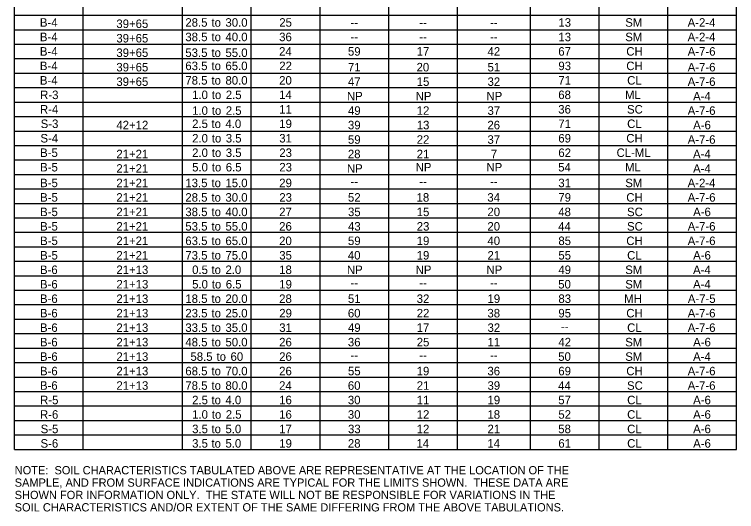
# Model space of a CAD drawing. Extents: x 977434 to 989596, y 1525697 to 1528336.
# Drawn here: x 977441 to 977967, y 1527523 to 1527885 of the extents above; entities that cross this region are included whole.
import ezdxf

# ---------------------------------------------------------------- set-up
doc = ezdxf.new("R2010")
doc.units = 0
doc.layers.add('Default', color=7, linetype='Continuous')

msp = doc.modelspace()

# ---------------------------------------------------------------- linework, layer by layer
at = {"layer": 'Default'}
for p, q in [((977441.26, 1527568.31), (977441.26, 1528234.33)), ((977441.26, 1527568.31), (977441.26, 1528234.33)), ((977966.88, 1527568.31), (977966.88, 1528234.33)), ((977966.88, 1527568.31), (977966.88, 1528234.33)), ((977491.28, 1527568.31), (977491.28, 1528221.17)), ((977563.67, 1527568.31), (977563.67, 1528221.17)), ((977613.69, 1527568.31), (977613.69, 1528221.17)), ((977663.71, 1527568.31), (977663.71, 1528221.17)), ((977816.83, 1527568.31), (977816.83, 1528221.17)), ((977866.85, 1527568.31), (977866.85, 1528221.17)), ((977916.87, 1527568.31), (977916.87, 1528221.17)), ((977713.72, 1527568.31), (977713.72, 1528210.64)), ((977763.74, 1527568.31), (977763.74, 1528210.64)), ((977441.26, 1527884.21), (977966.88, 1527884.21)), ((977441.26, 1527873.68), (977966.88, 1527873.68)), ((977441.26, 1527863.15), (977966.88, 1527863.15)), ((977441.26, 1527852.62), (977966.88, 1527852.62)), ((977441.26, 1527842.09), (977966.88, 1527842.09)), ((977441.26, 1527831.56), (977966.88, 1527831.56)), ((977441.26, 1527821.03), (977966.88, 1527821.03)), ((977441.26, 1527810.5), (977966.88, 1527810.5)), ((977441.26, 1527799.97), (977966.88, 1527799.97)), ((977441.26, 1527789.44), (977966.88, 1527789.44)), ((977441.26, 1527778.91), (977966.88, 1527778.91)), ((977441.26, 1527768.38), (977966.88, 1527768.38)), ((977441.26, 1527757.85), (977966.88, 1527757.85)), ((977441.26, 1527747.32), (977966.88, 1527747.32)), ((977441.26, 1527736.79), (977966.88, 1527736.79)), ((977441.26, 1527726.26), (977966.88, 1527726.26)), ((977441.26, 1527715.73), (977966.88, 1527715.73)), ((977441.26, 1527705.2), (977966.88, 1527705.2)), ((977441.26, 1527694.67), (977966.88, 1527694.67)), ((977441.26, 1527684.14), (977966.88, 1527684.14)), ((977441.26, 1527673.61), (977966.88, 1527673.61)), ((977441.26, 1527663.08), (977966.88, 1527663.08)), ((977441.26, 1527652.55), (977966.88, 1527652.55)), ((977441.26, 1527642.02), (977966.88, 1527642.02)), ((977441.26, 1527631.49), (977966.88, 1527631.49)), ((977441.26, 1527620.96), (977966.88, 1527620.96)), ((977441.26, 1527610.43), (977966.88, 1527610.43)), ((977441.26, 1527599.9), (977966.88, 1527599.9)), ((977441.26, 1527589.37), (977966.88, 1527589.37)), ((977441.26, 1527578.84), (977966.88, 1527578.84)), ((977441.26, 1527568.31), (977966.88, 1527568.31))]:
    msp.add_line(p, q, dxfattribs=at)

# ---------------------------------------------------------------- texts
for s, height, p in [('B-4', 6.188, (977459.79, 1527875.85)), ('39+65', 6.188, (977515.45, 1527874.92)), ('28.5', 6.188, (977565.66, 1527875.85)), (' to', 6.188, (977582.37, 1527875.85)), (' 30.0', 6.188, (977592.55, 1527875.85)), ('25', 6.188, (977634.04, 1527875.85)), ('13', 6.188, (977837.2, 1527875.85)), ('SM', 6.188, (977885.86, 1527875.85)), ('A-2-4', 6.188, (977931.27, 1527875.85)), ('--', 6.188, (977685.89, 1527875.85)), ('--', 6.188, (977735.91, 1527875.85)), ('--', 6.188, (977787.46, 1527875.85)), ('B-4', 6.188, (977459.79, 1527865.32)), ('39+65', 6.188, (977515.45, 1527864.39)), ('38.5', 6.188, (977565.66, 1527865.32)), (' to', 6.188, (977582.37, 1527865.32)), (' 40.0', 6.188, (977592.55, 1527865.32)), ('36', 6.188, (977633.95, 1527865.32)), ('13', 6.188, (977837.2, 1527865.32)), ('SM', 6.188, (977885.86, 1527865.32)), ('A-2-4', 6.188, (977931.27, 1527865.32)), ('--', 6.188, (977685.89, 1527865.32)), ('--', 6.188, (977735.91, 1527865.32)), ('--', 6.188, (977787.46, 1527865.32)), ('B-4', 6.188, (977459.79, 1527854.79)), ('39+65', 6.188, (977515.45, 1527853.86)), ('53.5', 6.188, (977565.66, 1527853.86)), (' to', 6.188, (977582.37, 1527853.86)), (' 55.0', 6.188, (977592.55, 1527853.86)), ('24', 6.188, (977633.9, 1527854.79)), ('59', 6.188, (977684.02, 1527854.79)), ('17', 6.188, (977734.02, 1527854.79)), ('42', 6.188, (977785.62, 1527854.79)), ('67', 6.188, (977837.12, 1527854.79)), ('CH', 6.188, (977886.63, 1527854.79)), ('A-7-6', 6.188, (977931.32, 1527854.79)), ('B-4', 6.188, (977459.79, 1527844.26)), ('39+65', 6.188, (977515.45, 1527843.33)), ('63.5', 6.188, (977565.66, 1527844.26)), (' to', 6.188, (977582.37, 1527844.26)), (' 65.0', 6.188, (977592.55, 1527844.26)), ('22', 6.188, (977634.03, 1527844.26)), ('71', 6.188, (977684.04, 1527843.33)), ('20', 6.188, (977733.96, 1527843.33)), ('51', 6.188, (977785.61, 1527843.33)), ('93', 6.188, (977837.2, 1527844.26)), ('CH', 6.188, (977886.63, 1527844.26)), ('A-7-6', 6.188, (977931.32, 1527843.33)), ('B-4', 6.188, (977459.79, 1527833.73)), ('39+65', 6.188, (977515.45, 1527832.8)), ('78.5', 6.188, (977565.66, 1527833.73)), (' to', 6.188, (977582.37, 1527833.73)), (' 80.0', 6.188, (977592.55, 1527833.73)), ('20', 6.188, (977633.93, 1527833.73)), ('47', 6.188, (977684, 1527832.8)), ('15', 6.188, (977734.08, 1527832.8)), ('32', 6.188, (977785.62, 1527832.8)), ('71', 6.188, (977837.16, 1527833.73)), ('CL', 6.188, (977887.25, 1527833.73)), ('A-7-6', 6.188, (977931.32, 1527832.8)), ('R-3', 6.188, (977459.96, 1527823.2)), ('1.0', 6.188, (977570.6, 1527823.2)), (' to', 6.188, (977582.61, 1527823.2)), (' 2.5', 6.188, (977592.78, 1527823.2)), ('14', 6.188, (977633.9, 1527823.2)), ('NP', 6.188, (977683.27, 1527822.27)), ('NP', 6.188, (977733.29, 1527822.27)), ('NP', 6.188, (977784.84, 1527822.27)), ('68', 6.188, (977837.1, 1527823.2)), ('ML', 6.188, (977885.68, 1527823.2)), ('A-4', 6.188, (977935.23, 1527822.27)), ('R-4', 6.188, (977459.8, 1527812.67)), ('1.0', 6.188, (977570.6, 1527811.74)), (' to', 6.188, (977582.61, 1527811.74)), (' 2.5', 6.188, (977592.78, 1527811.74)), ('11', 6.188, (977634.02, 1527812.67)), ('49', 6.188, (977684.02, 1527811.74)), ('12', 6.188, (977734.06, 1527811.74)), ('37', 6.188, (977785.57, 1527811.74)), ('36', 6.188, (977837.09, 1527812.67)), ('SC', 6.188, (977887.15, 1527812.67)), ('A-7-6', 6.188, (977931.32, 1527811.74)), ('S-3', 6.188, (977460.36, 1527802.14)), ('42+12', 6.188, (977515.44, 1527801.21)), ('2.5', 6.188, (977570.6, 1527802.14)), (' to', 6.188, (977582.37, 1527802.14)), (' 4.0', 6.188, (977592.55, 1527802.14)), ('19', 6.188, (977634.01, 1527802.14)), ('39', 6.188, (977684.02, 1527801.21)), ('13', 6.188, (977734.09, 1527801.21)), ('26', 6.188, (977785.54, 1527801.21)), ('71', 6.188, (977837.16, 1527802.14)), ('CL', 6.188, (977887.25, 1527802.14)), ('A-6', 6.188, (977935.28, 1527801.21)), ('S-4', 6.188, (977460.21, 1527791.61)), ('2.0', 6.188, (977570.6, 1527791.61)), (' to', 6.188, (977582.61, 1527791.61)), (' 3.5', 6.188, (977592.78, 1527791.61)), ('31', 6.188, (977634.02, 1527791.61)), ('59', 6.188, (977684.02, 1527790.68)), ('22', 6.188, (977734.06, 1527790.68)), ('37', 6.188, (977785.57, 1527790.68)), ('69', 6.188, (977837.15, 1527791.61)), ('CH', 6.188, (977886.63, 1527791.61)), ('A-7-6', 6.188, (977931.32, 1527790.68)), ('B-5', 6.188, (977459.94, 1527781.08)), ('21+21', 6.188, (977515.43, 1527780.15)), ('2.0', 6.188, (977570.6, 1527781.08)), (' to', 6.188, (977582.61, 1527781.08)), (' 3.5', 6.188, (977592.78, 1527781.08)), ('23', 6.188, (977634.06, 1527781.08)), ('28', 6.188, (977683.98, 1527780.15)), ('21', 6.188, (977734.06, 1527780.15)), ('7', 6.19, (977788.04, 1527780.15)), ('62', 6.188, (977837.17, 1527781.08)), ('CL-ML', 6.188, (977879.54, 1527781.08)), ('A-4', 6.188, (977935.23, 1527780.15)), ('B-5', 6.188, (977459.94, 1527770.55)), ('21+21', 6.188, (977515.43, 1527769.62)), ('5.0', 6.188, (977570.6, 1527770.55)), (' to', 6.188, (977582.61, 1527770.55)), (' 6.5', 6.188, (977592.78, 1527770.55)), ('23', 6.188, (977634.06, 1527770.55)), ('NP', 6.188, (977683.27, 1527769.62)), ('NP', 6.188, (977733.29, 1527770.55)), ('NP', 6.188, (977784.84, 1527770.55)), ('54', 6.188, (977837.04, 1527770.55)), ('ML', 6.188, (977885.68, 1527770.55)), ('A-4', 6.188, (977935.23, 1527769.62)), ('B-5', 6.188, (977459.94, 1527759.09)), ('21+21', 6.188, (977515.43, 1527759.09)), ('13.5', 6.188, (977565.66, 1527759.09)), (' to', 6.188, (977582.37, 1527759.09)), (' 15.0', 6.188, (977592.55, 1527759.09)), ('29', 6.188, (977634.01, 1527759.09)), ('31', 6.188, (977837.16, 1527759.09)), ('SM', 6.188, (977885.86, 1527759.09)), ('A-2-4', 6.188, (977931.27, 1527759.09)), ('--', 6.188, (977685.89, 1527760.02)), ('--', 6.188, (977735.91, 1527760.02)), ('--', 6.188, (977787.46, 1527760.02)), ('B-5', 6.188, (977459.94, 1527748.56)), ('21+21', 6.188, (977515.43, 1527748.56)), ('28.5', 6.188, (977565.66, 1527748.56)), (' to', 6.188, (977582.37, 1527748.56)), (' 30.0', 6.188, (977592.55, 1527748.56)), ('23', 6.188, (977634.06, 1527748.56)), ('52', 6.188, (977684.05, 1527748.56)), ('18', 6.188, (977733.99, 1527748.56)), ('34', 6.188, (977785.49, 1527748.56)), ('79', 6.188, (977837.15, 1527748.56)), ('CH', 6.188, (977886.63, 1527748.56)), ('A-7-6', 6.188, (977931.32, 1527748.56)), ('B-5', 6.188, (977459.94, 1527738.03)), ('21+21', 6.188, (977515.43, 1527738.03)), ('38.5', 6.188, (977565.66, 1527738.03)), (' to', 6.188, (977582.37, 1527738.03)), (' 40.0', 6.188, (977592.55, 1527738.03)), ('27', 6.188, (977633.98, 1527738.03)), ('35', 6.188, (977684.06, 1527738.03)), ('15', 6.188, (977734.08, 1527738.03)), ('20', 6.188, (977785.52, 1527738.03)), ('48', 6.188, (977837.1, 1527738.03)), ('SC', 6.188, (977887.15, 1527738.03)), ('A-6', 6.188, (977935.28, 1527738.03)), ('B-5', 6.188, (977459.94, 1527727.5)), ('21+21', 6.188, (977515.43, 1527727.5)), ('53.5', 6.188, (977565.66, 1527727.5)), (' to', 6.188, (977582.37, 1527727.5)), (' 55.0', 6.188, (977592.55, 1527727.5)), ('26', 6.188, (977633.95, 1527727.5)), ('43', 6.188, (977684.07, 1527727.5)), ('23', 6.188, (977734.09, 1527727.5)), ('20', 6.188, (977785.52, 1527727.5)), ('44', 6.188, (977837.04, 1527727.5)), ('SC', 6.188, (977887.15, 1527727.5)), ('A-7-6', 6.188, (977931.32, 1527727.5)), ('B-5', 6.188, (977459.94, 1527716.97)), ('21+21', 6.188, (977515.43, 1527716.97)), ('63.5', 6.188, (977565.66, 1527716.97)), (' to', 6.188, (977582.37, 1527716.97)), (' 65.0', 6.188, (977592.55, 1527716.97)), ('20', 6.188, (977633.93, 1527716.97)), ('59', 6.188, (977684.02, 1527716.97)), ('19', 6.188, (977734.04, 1527716.97)), ('40', 6.188, (977785.52, 1527716.97)), ('85', 6.188, (977837.19, 1527716.97)), ('CH', 6.188, (977886.63, 1527716.97)), ('A-7-6', 6.188, (977931.32, 1527716.97)), ('B-5', 6.188, (977459.94, 1527706.44)), ('21+21', 6.188, (977515.43, 1527706.44)), ('73.5', 6.188, (977565.66, 1527706.44)), (' to', 6.188, (977582.37, 1527706.44)), (' 75.0', 6.188, (977592.55, 1527706.44)), ('35', 6.188, (977634.04, 1527706.44)), ('40', 6.188, (977683.95, 1527706.44)), ('19', 6.188, (977734.04, 1527706.44)), ('21', 6.188, (977785.61, 1527706.44)), ('55', 6.188, (977837.19, 1527706.44)), ('CL', 6.188, (977887.25, 1527706.44)), ('A-6', 6.188, (977935.28, 1527706.44)), ('B-6', 6.188, (977459.85, 1527695.91)), ('21+13', 6.188, (977515.47, 1527695.91)), ('0.5', 6.188, (977570.6, 1527695.91)), (' to', 6.188, (977582.37, 1527695.91)), (' 2.0', 6.188, (977592.55, 1527695.91)), ('18', 6.188, (977633.96, 1527695.91)), ('NP', 6.188, (977683.27, 1527695.91)), ('NP', 6.188, (977733.29, 1527695.91)), ('NP', 6.188, (977784.84, 1527695.91)), ('49', 6.188, (977837.15, 1527695.91)), ('SM', 6.188, (977885.86, 1527695.91)), ('A-4', 6.188, (977935.23, 1527695.91)), ('B-6', 6.188, (977459.85, 1527685.38)), ('21+13', 6.188, (977515.47, 1527685.38)), ('5.0', 6.188, (977570.6, 1527685.38)), (' to', 6.188, (977582.61, 1527685.38)), (' 6.5', 6.188, (977592.78, 1527685.38)), ('19', 6.188, (977634.01, 1527685.38)), ('50', 6.188, (977837.07, 1527685.38)), ('SM', 6.188, (977885.86, 1527685.38)), ('A-4', 6.188, (977935.23, 1527685.38)), ('--', 6.188, (977685.89, 1527686.31)), ('--', 6.188, (977735.91, 1527686.31)), ('--', 6.188, (977787.46, 1527686.31)), ('B-6', 6.188, (977459.85, 1527674.85)), ('21+13', 6.188, (977515.47, 1527674.85)), ('18.5', 6.188, (977565.66, 1527674.85)), (' to', 6.188, (977582.37, 1527674.85)), (' 20.0', 6.188, (977592.55, 1527674.85)), ('28', 6.188, (977633.96, 1527674.85)), ('51', 6.188, (977684.04, 1527674.85)), ('32', 6.188, (977734.06, 1527674.85)), ('19', 6.188, (977785.59, 1527674.85)), ('83', 6.188, (977837.2, 1527674.85)), ('MH', 6.188, (977885.06, 1527674.85)), ('A-7-5', 6.188, (977931.41, 1527674.85)), ('B-6', 6.188, (977459.85, 1527664.32)), ('21+13', 6.188, (977515.47, 1527664.32)), ('23.5', 6.188, (977565.66, 1527664.32)), (' to', 6.188, (977582.37, 1527664.32)), (' 25.0', 6.188, (977592.55, 1527664.32)), ('29', 6.188, (977634.01, 1527664.32)), ('60', 6.188, (977683.95, 1527664.32)), ('22', 6.188, (977734.06, 1527664.32)), ('38', 6.188, (977785.55, 1527664.32)), ('95', 6.188, (977837.19, 1527664.32)), ('CH', 6.188, (977886.63, 1527664.32)), ('A-7-6', 6.188, (977931.32, 1527664.32)), ('B-6', 6.188, (977459.85, 1527653.79)), ('21+13', 6.188, (977515.47, 1527653.79)), ('33.5', 6.188, (977565.66, 1527653.79)), (' to', 6.188, (977582.37, 1527653.79)), (' 35.0', 6.188, (977592.55, 1527653.79)), ('31', 6.188, (977634.02, 1527653.79)), ('49', 6.188, (977684.02, 1527653.79)), ('17', 6.188, (977734.02, 1527653.79)), ('32', 6.188, (977785.62, 1527653.79)), ('CL', 6.188, (977887.25, 1527653.79)), ('A-7-6', 6.188, (977931.32, 1527653.79)), ('--', 6.188, (977839.02, 1527654.72)), ('B-6', 6.188, (977459.85, 1527643.26)), ('21+13', 6.188, (977515.47, 1527643.26)), ('48.5', 6.188, (977565.66, 1527643.26)), (' to', 6.188, (977582.37, 1527643.26)), (' 50.0', 6.188, (977592.55, 1527643.26)), ('26', 6.188, (977633.95, 1527643.26)), ('36', 6.188, (977683.97, 1527643.26)), ('25', 6.188, (977734.08, 1527643.26)), ('11', 6.188, (977785.61, 1527643.26)), ('42', 6.188, (977837.17, 1527643.26)), ('SM', 6.188, (977885.86, 1527643.26)), ('A-6', 6.188, (977935.28, 1527643.26)), ('B-6', 6.188, (977459.85, 1527632.73)), ('21+13', 6.188, (977515.47, 1527632.73)), ('58.5', 6.188, (977569.37, 1527632.73)), (' to', 6.188, (977586.07, 1527632.73)), (' 60', 6.188, (977596.25, 1527632.73)), ('26', 6.188, (977633.95, 1527632.73)), ('50', 6.188, (977837.07, 1527632.73)), ('SM', 6.188, (977885.86, 1527632.73)), ('A-4', 6.188, (977935.23, 1527632.73)), ('--', 6.188, (977685.89, 1527633.66)), ('--', 6.188, (977735.91, 1527633.66)), ('--', 6.188, (977787.46, 1527633.66)), ('B-6', 6.188, (977459.85, 1527622.2)), ('21+13', 6.188, (977515.47, 1527622.2)), ('68.5', 6.188, (977565.66, 1527622.2)), (' to', 6.188, (977582.37, 1527622.2)), (' 70.0', 6.188, (977592.55, 1527622.2)), ('26', 6.188, (977633.95, 1527622.2)), ('55', 6.188, (977684.06, 1527622.2)), ('19', 6.188, (977734.04, 1527622.2)), ('36', 6.188, (977785.54, 1527622.2)), ('69', 6.188, (977837.15, 1527622.2)), ('CH', 6.188, (977886.63, 1527622.2)), ('A-7-6', 6.188, (977931.32, 1527622.2)), ('B-6', 6.188, (977459.85, 1527611.67)), ('21+13', 6.188, (977515.47, 1527611.67)), ('78.5', 6.188, (977565.66, 1527611.67)), (' to', 6.188, (977582.37, 1527611.67)), (' 80.0', 6.188, (977592.55, 1527611.67)), ('24', 6.188, (977633.9, 1527611.67)), ('60', 6.188, (977683.95, 1527611.67)), ('21', 6.188, (977734.06, 1527611.67)), ('39', 6.188, (977785.59, 1527611.67)), ('44', 6.188, (977837.04, 1527611.67)), ('SC', 6.188, (977887.15, 1527611.67)), ('A-7-6', 6.188, (977931.32, 1527611.67)), ('R-5', 6.188, (977459.94, 1527601.14)), ('2.5', 6.188, (977570.6, 1527601.14)), (' to', 6.188, (977582.37, 1527601.14)), (' 4.0', 6.188, (977592.55, 1527601.14)), ('16', 6.188, (977633.95, 1527601.14)), ('30', 6.188, (977683.95, 1527601.14)), ('11', 6.188, (977734.06, 1527601.14)), ('19', 6.188, (977785.59, 1527601.14)), ('57', 6.188, (977837.12, 1527601.14)), ('CL', 6.188, (977887.25, 1527601.14)), ('A-6', 6.188, (977935.28, 1527601.14)), ('R-6', 6.188, (977459.85, 1527590.61)), ('1.0', 6.188, (977570.6, 1527590.61)), (' to', 6.188, (977582.61, 1527590.61)), (' 2.5', 6.188, (977592.78, 1527590.61)), ('16', 6.188, (977633.95, 1527590.61)), ('30', 6.188, (977683.95, 1527590.61)), ('12', 6.188, (977734.06, 1527590.61)), ('18', 6.188, (977785.55, 1527590.61)), ('52', 6.188, (977837.17, 1527590.61)), ('CL', 6.188, (977887.25, 1527590.61)), ('A-6', 6.188, (977935.28, 1527590.61)), ('S-5', 6.188, (977460.35, 1527580.08)), ('3.5', 6.188, (977570.6, 1527580.08)), (' to', 6.188, (977582.37, 1527580.08)), (' 5.0', 6.188, (977592.55, 1527580.08)), ('17', 6.188, (977633.98, 1527580.08)), ('33', 6.188, (977684.07, 1527580.08)), ('12', 6.188, (977734.06, 1527580.08)), ('21', 6.188, (977785.61, 1527580.08)), ('58', 6.188, (977837.1, 1527580.08)), ('CL', 6.188, (977887.25, 1527580.08)), ('A-6', 6.188, (977935.28, 1527580.08)), ('S-6', 6.188, (977460.26, 1527569.55)), ('3.5', 6.188, (977570.6, 1527569.55)), (' to', 6.188, (977582.37, 1527569.55)), (' 5.0', 6.188, (977592.55, 1527569.55)), ('19', 6.188, (977634.01, 1527569.55)), ('28', 6.188, (977683.98, 1527569.55)), ('14', 6.188, (977733.93, 1527569.55)), ('14', 6.188, (977785.49, 1527569.55)), ('61', 6.188, (977837.16, 1527569.55)), ('CL', 6.188, (977887.25, 1527569.55)), ('A-6', 6.188, (977935.28, 1527569.55)), ('NOTE:  SOIL CHARACTERISTICS TABULATED ABOVE ARE REPRESENTATIVE AT THE LOCATION OF THE', 6, (977441.43, 1527550.14)), ('SAMPLE, AND FROM SURFACE INDICATIONS ARE TYPICAL FOR THE LIMITS SHOWN.  THESE DATA ARE ', 6, (977441.43, 1527541.14)), ('SHOWN FOR INFORMATION ONLY.  THE STATE WILL NOT BE RESPONSIBLE FOR VARIATIONS IN THE ', 6, (977441.43, 1527532.14)), ('SOIL CHARACTERISTICS AND/OR EXTENT OF THE SAME DIFFERING FROM THE ABOVE TABULATIONS.', 6, (977441.43, 1527523.14))]:
    msp.add_text(s, height=height, dxfattribs=at).set_placement(p)

doc.saveas('drawing.dxf')
